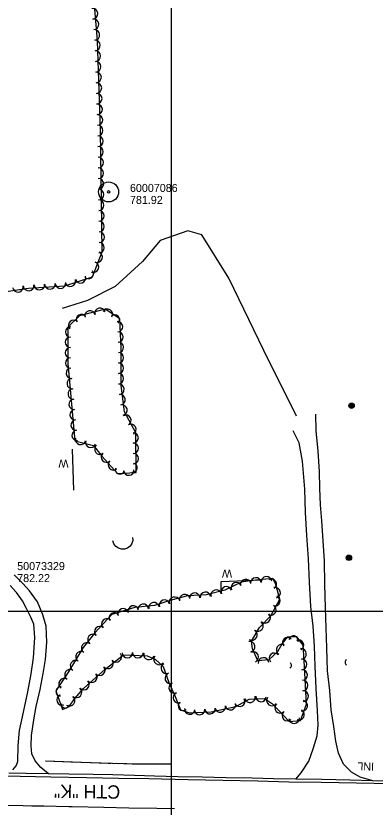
# Model space of a CAD drawing. Extents: x 591954 to 597000, y 198576 to 213500.
# Drawn here: x 592883 to 593152, y 204853 to 205446 of the extents above; entities that cross this region are included whole.
import ezdxf

# ---------------------------------------------------------------- set-up
doc = ezdxf.new("R2010")
doc.units = 0
for name, color, linetype in [('Level 10', 7, 'Continuous'), ('Level 11', 7, 'Continuous'), ('Level 12', 7, 'Continuous'), ('Level 14', 7, 'Continuous'), ('Level 15', 7, 'Continuous'), ('Level 17', 7, 'Continuous'), ('Level 18', 7, 'Continuous'), ('Level 19', 7, 'Continuous'), ('Level 3', 7, 'Continuous'), ('Level 6', 7, 'Continuous')]:
    doc.layers.add(name, color=color, linetype=linetype)

msp = doc.modelspace()

# ---------------------------------------------------------------- linework, layer by layer
at = {"layer": 'Level 10'}
for p, q in [((593000, 204500), (593000, 206000)), ((592000, 205000), (594000, 205000)), ((592000, 205000), (594000, 205000)), ((593000, 203500), (593000, 205000))]:
    msp.add_line(p, q, dxfattribs=at)
at = {"layer": 'Level 11'}
for points in [[(592724.48, 204879.47), (592725.78, 204879.44), (592741.99, 204879.18), (592763.93, 204878.81), (592780.35, 204878.35), (592798.44, 204878.1), (592816.58, 204877.66), (592846.97, 204877.14), (592865.91, 204876.86), (592886.57, 204876.35), (592909.64, 204875.89), (592936.24, 204875.46), (592960.11, 204874.97), (592983.05, 204874.55), (593012.39, 204873.93), (593038.27, 204873.38), (593064.7, 204872.76), (593087.76, 204872.24), (593112.14, 204871.86), (593138.46, 204871.33), (593164.84, 204870.93)], [(593165.37, 204872.59), (593150.8, 204872.76), (593133.45, 204873.25), (593112.63, 204873.78), (593093.15, 204874.12), (593076.42, 204874.43), (593060.27, 204874.94), (593040.92, 204875.23), (593023.03, 204875.6), (593004.69, 204875.96), (592987.26, 204876.44), (592972.27, 204876.83), (592956.03, 204877.24), (592941.19, 204877.5), (592922.95, 204877.85), (592907.87, 204878.05), (592891.06, 204878.27), (592878.05, 204878.66)], [(592895.38, 204853.95), (592888.74, 204854.02), (592868.89, 204854.3)], [(592923.03, 204853.33), (592904.37, 204853.84), (592895.38, 204853.95)], [(593002.1, 204851.87), (592988.95, 204852.07), (592967.96, 204852.44), (592949.24, 204852.79), (592925.52, 204853.26), (592923.03, 204853.33)]]:
    msp.add_lwpolyline(points, dxfattribs=at)
at = {"layer": 'Level 12'}
msp.add_lwpolyline([(592970.84, 205055.37), (592970.9, 205053.02), (592970.22, 205050.77), (592968.88, 205048.84), (592967.02, 205047.42), (592964.8, 205046.64), (592962.45, 205046.59), (592960.2, 205047.27), (592958.27, 205048.61), (592956.85, 205050.48), (592956.07, 205052.7)], dxfattribs=at)
at = {"layer": 'Level 14'}
for centre, radius in [((593134.82, 205154.08), 2.02), ((593134.82, 205154.1), 1.52), ((593134.83, 205154.06), 1.01), ((593134.83, 205154.07), 0.502), ((593132.79, 205040.08), 2.02), ((593132.79, 205040.09), 1.52), ((593132.79, 205040.05), 1.01), ((593132.8, 205040.06), 0.502)]:
    msp.add_circle(centre, radius, dxfattribs=at)
at = {"layer": 'Level 15'}
for points in [[(592925.44, 205121.49), (592926.45, 205090.87)], [(593037.15, 205014.76), (593037.13, 205022.26), (593055.37, 205022.94), (593067.36, 205023.53)]]:
    msp.add_lwpolyline(points, dxfattribs=at)
for centre, start, end in [((593132.43, 204961.86), 128.87943, 235.11899), ((593087.34, 204959.51), 302.27944, 48.519)]:
    msp.add_arc(centre, 2.5, start, end, dxfattribs=at)
at = {"layer": 'Level 17'}
for points in [[(593093.68, 205146.24), (593069.14, 205195.41), (593042.97, 205249.64), (593022.68, 205282.31), (593012.13, 205285.23), (592991.4, 205277.93), (592978.3, 205262.29), (592957.67, 205243.58), (592937.04, 205232.99), (592918.09, 205227.11)], [(593150.8, 204872.76), (593141.2, 204875.62), (593134.78, 204879.29), (593128.77, 204885.4), (593125.07, 204893.56), (593123.13, 204902.73), (593121.45, 204913.58), (593119.56, 204926.09), (593118.43, 204940.58), (593116.83, 204955.29), (593116.25, 204972.61), (593115.73, 204987.62), (593115.21, 205002.64), (593114.84, 205020.19), (593114.45, 205037.69), (593113.47, 205052.69), (593112.66, 205067.76), (593111.61, 205079.84), (593111.17, 205092.35), (593110.74, 205104.86), (593109.8, 205120.08), (593108.33, 205135.3), (593107.96, 205147.79)], [(593093.15, 204874.12), (593097.19, 204878.9), (593102.89, 204887.52), (593106.02, 204896.74), (593109, 204906.55), (593109.69, 204914.55), (593109.25, 204925.64), (593108.42, 204941.99), (593107.5, 204958.77), (593107.07, 204973.86), (593106.14, 204988.73), (593104.32, 205003.61), (593103.34, 205021.83), (593102.52, 205039.34), (593101.19, 205056.71), (593100.44, 205074.08), (593099.83, 205091.6), (593098.19, 205112.48), (593095.5, 205126.35), (593091.16, 205135.15)], [(592907.87, 204878.05), (592902.05, 204882.74), (592897.69, 204887.79), (592895.42, 204893.2), (592894.81, 204899.01), (592895.12, 204906.76), (592896.69, 204918.67), (592898.67, 204928.62), (592901.44, 204941.39), (592903.8, 204953.37), (592905.52, 204963.88), (592906.49, 204976.87), (592905.94, 204988.75), (592903.44, 204997.33), (592899.59, 205007), (592893.53, 205015.23), (592888.69, 205020.72), (592882.2, 205027.34)], [(592881.07, 204881.02), (592883.67, 204884.2), (592884.77, 204887.31), (592885, 204899.41), (592886.16, 204910.59), (592888.95, 204924.23), (592892.29, 204939.55), (592894.89, 204953.12), (592896.55, 204965.1), (592897.45, 204980.33), (592896.76, 204990.31), (592894.45, 204995.5), (592891.39, 205002.12), (592888.2, 205007.84), (592883.79, 205014.12), (592879.19, 205019.23)]]:
    msp.add_lwpolyline(points, dxfattribs=at)
at = {"layer": 'Level 18'}
for points in [[(592867.59, 205238.56), (592892.8, 205242.34), (592920.02, 205244.06), (592940.88, 205250.78), (592947.96, 205269.6), (592947.41, 205307.89), (592946.75, 205360.3), (592944.59, 205427.95), (592941.72, 205460.35)], [(592927.47, 205127.86), (592941.52, 205124.28), (592947.8, 205116.18), (592959.47, 205103.24), (592973.37, 205104.11), (592973.31, 205133.71), (592964.64, 205149.46), (592962.21, 205169.31), (592962.21, 205196.98), (592961.25, 205219.19), (592950.16, 205226.55), (592930.99, 205221.43), (592922.19, 205213), (592922.17, 205185.72), (592927.47, 205127.86)], [(593059.91, 204977.68), (593065.97, 204987.93), (593074.23, 204996.49), (593081.1, 205009.11), (593077.83, 205020.89), (593075.87, 205024.65), (593060.39, 205023.09), (593052.27, 205021.74), (593039.99, 205015.9), (593026.19, 205012.28), (593011.94, 205011.54), (592999.72, 205008.26), (592987.18, 205004.44), (592972.39, 205002.86), (592955.3, 204997.58), (592942.47, 204983.92), (592933.86, 204972.79), (592922.38, 204953.82), (592913.32, 204940.3), (592918.35, 204926.4), (592923.16, 204928.55), (592927.41, 204934.5), (592934.06, 204942.18), (592949.96, 204956.32), (592963.9, 204967.4), (592981.63, 204966.52), (592988.01, 204963.84), (592993.75, 204958.67), (592997.9, 204946.48), (593002.67, 204936.05), (593006.64, 204926.13), (593013.39, 204923.85), (593029.71, 204924.7), (593048.1, 204928.63), (593058.12, 204934.06), (593069.52, 204934.6), (593075.7, 204930.56), (593088.01, 204917.44), (593096.6, 204918.13), (593100.96, 204930.23), (593099.38, 204963.16), (593098.55, 204974.55), (593093.88, 204980.92), (593086.5, 204980.47), (593082.89, 204975.79), (593079.33, 204969.62), (593072.95, 204963.69), (593064.61, 204962.92), (593060.58, 204971.78), (593059.91, 204977.68)]]:
    msp.add_lwpolyline(points, dxfattribs=at)
for centre, radius, start, end in [((592940.71, 205448.01), 4, 275.06839, 95.05306), ((592941.42, 205440.05), 4, 275.06187, 95.04655), ((592942.12, 205432.09), 4, 275.06902, 95.05369), ((592942.61, 205424.23), 4, 271.97988, 91.96456), ((592942.87, 205416.25), 4, 271.82892, 91.8136), ((592943.12, 205408.26), 4, 271.83632, 91.82099), ((592943.38, 205400.28), 4, 271.83632, 91.82099), ((592943.63, 205392.29), 4, 271.83632, 91.82099), ((592943.89, 205384.3), 4, 271.83609, 91.82076), ((592944.14, 205376.32), 4, 271.82915, 91.81383), ((592944.4, 205368.33), 4, 271.83632, 91.82099), ((592944.62, 205360.36), 4, 271.29837, 91.28305), ((592944.76, 205352.39), 4, 270.7318, 90.71648), ((592944.86, 205344.4), 4, 270.7318, 90.71648), ((592944.96, 205336.41), 4, 270.72472, 90.70939), ((592945.06, 205328.42), 4, 270.7318, 90.71648), ((592945.16, 205320.43), 4, 270.7318, 90.71648), ((592945.26, 205312.44), 4, 270.7318, 90.71648), ((592945.37, 205304.44), 4, 270.83226, 90.81694), ((592945.48, 205296.45), 4, 270.83933, 90.82401), ((592945.6, 205288.46), 4, 270.83943, 90.82411), ((592945.72, 205280.47), 4, 270.84649, 90.83117), ((592945.65, 205272.62), 3.96, 267.96122, 87.9459), ((592944.22, 205265.58), 4, 249.37526, 69.35993), ((592941.4, 205258.1), 4, 249.38196, 69.36664), ((592937.92, 205252.96), 3.62, 217.04204, 37.02672), ((592924.12, 205247.58), 4, 197.87579, 17.86047), ((592931.72, 205250.03), 4, 197.87579, 17.86047), ((592884.87, 205243.27), 4, 188.52814, 8.51282), ((592892.89, 205244.28), 3.99, 185.90248, 5.88716), ((592900.93, 205244.95), 4, 183.6238, 3.60848), ((592908.91, 205245.45), 4, 183.62335, 3.60803), ((592916.8, 205246.06), 3.98, 185.35319, 5.33787), ((592938.93, 205221.44), 3.9, 14.95043, 194.93511), ((592946.47, 205223.45), 3.9, 14.95043, 194.93511), ((592951.96, 205222.74), 3.83, 329.02081, 149.00548), ((592926.68, 205214.47), 3.9, 43.78216, 223.76684), ((592932.34, 205218.81), 3.78, 29.82589, 209.81057), ((592957.46, 205218.6), 3.6, 314.51816, 134.50284), ((592959.46, 205213.37), 3.9, 272.49785, 92.48253), ((592924.33, 205209.33), 3.85, 88.02708, 268.01176), ((592924.22, 205201.65), 3.9, 89.96361, 269.94828), ((592959.8, 205205.57), 3.9, 272.49753, 92.48221), ((592960.07, 205197.81), 3.9, 271.52824, 91.51291), ((592924.21, 205193.85), 3.9, 89.97095, 269.95563), ((592960.17, 205190.06), 3.9, 270.00032, 89.985), ((592924.37, 205186.14), 3.9, 92.38259, 272.36727), ((592924.88, 205178.46), 3.9, 95.24264, 275.22732), ((592960.17, 205182.26), 3.9, 269.99298, 89.97765), ((592960.17, 205174.46), 3.9, 269.99298, 89.97765), ((592925.59, 205170.69), 3.9, 95.236, 275.22068), ((592960.58, 205166.47), 3.9, 275.87549, 95.86016), ((592926.3, 205162.92), 3.9, 95.24264, 275.22732), ((592927.02, 205155.15), 3.9, 95.24331, 275.22799), ((592961.45, 205158.68), 3.9, 276.99333, 96.97801), ((592962.86, 205150.86), 3.85, 283.02462, 103.00929), ((592927.73, 205147.38), 3.9, 95.24331, 275.22799), ((592965.78, 205143.16), 3.9, 298.83904, 118.82372), ((592928.44, 205139.61), 3.9, 95.24264, 275.22732), ((592969.54, 205136.32), 3.9, 298.84258, 118.82726), ((592929.13, 205131.88), 3.86, 95.2431, 275.22778), ((592931.84, 205128.85), 3.9, 165.73989, 345.72457), ((592971.23, 205129.97), 3.89, 270.86957, 90.85425), ((592939.36, 205126.49), 3.79, 160.1923, 340.17698), ((592946.26, 205121.51), 3.9, 127.78668, 307.77136), ((592971.29, 205122.21), 3.9, 270.12514, 90.10982), ((592951.14, 205115.59), 3.9, 131.36426, 311.34894), ((592971.31, 205114.41), 3.9, 270.13249, 90.11717), ((592956.32, 205109.79), 3.9, 132.04673, 312.0314), ((592970.97, 205107.63), 3.32, 257.9527, 77.93738), ((592961.32, 205106.3), 3.53, 163.62773, 343.61241), ((592967.95, 205105.81), 3.9, 183.58629, 3.57096), ((593048.57, 205017.68), 3.97, 25.46977, 205.45444), ((593055.55, 205020.04), 3.95, 11.65152, 191.6362), ((593063.18, 205021.24), 3.97, 6.39087, 186.37555), ((593071.06, 205022.07), 3.97, 5.73548, 185.72015), ((593075.05, 205020.47), 3.61, 301.12911, 121.11379), ((593033.38, 205012.02), 3.97, 14.71379, 194.69846), ((593041.12, 205014.51), 3.96, 20.85277, 200.83745), ((593077.6, 205013.97), 3.97, 285.49047, 105.47515), ((593002.24, 205006.75), 3.97, 15.49934, 195.48402), ((593009.84, 205008.69), 3.96, 13.08251, 193.06719), ((593017.3, 205009.74), 3.97, 2.96549, 182.95017), ((593025.35, 205010.46), 3.95, 7.2819, 187.26658), ((593077.51, 205007.81), 3.79, 250.15324, 70.13792), ((592971.25, 205000.12), 3.96, 14.11939, 194.10407), ((592978.75, 205001.45), 3.97, 6.09858, 186.08326), ((592986.75, 205002.62), 3.96, 10.48806, 190.47274), ((592994.66, 205004.55), 3.97, 16.95767, 196.94235), ((593074.36, 205001.08), 3.97, 241.46512, 61.4498), ((592957.06, 204995.11), 3.84, 31.12363, 211.1083), ((592963.72, 204998), 3.97, 17.20423, 197.18891), ((593070.05, 204995.16), 3.97, 226.24759, 46.23227), ((592951.53, 204990.53), 3.97, 46.79279, 226.77747), ((593064.76, 204988.98), 3.95, 232.54089, 52.52557), ((592946.14, 204984.73), 3.97, 47.41612, 227.40079), ((592941.14, 204978.79), 3.97, 52.29397, 232.27864), ((593060.19, 204982.23), 3.97, 239.4211, 59.40578), ((593086.84, 204976.63), 3.72, 42.0738, 222.05848), ((593091.38, 204977.97), 3.57, 347.44754, 167.43222), ((592936.45, 204972.49), 3.97, 54.52456, 234.50923), ((593058.64, 204973.47), 3.89, 280.83259, 100.81726), ((593082.41, 204971.14), 3.95, 57.77331, 237.75798), ((593095.2, 204974.69), 3.84, 296.74277, 116.72745), ((592932.18, 204965.99), 3.97, 58.83243, 238.81711), ((592958.63, 204965.87), 3.97, 218.49741, 38.48209), ((592966.79, 204968.9), 3.85, 182.59638, 2.58106), ((592974.8, 204968.94), 3.97, 177.15786, 357.14254), ((592982.98, 204967.61), 3.92, 164.6531, 344.63778), ((593061.2, 204965.6), 3.93, 295.39233, 115.37701), ((593076.97, 204964.74), 3.94, 41.60922, 221.59389), ((593096.94, 204968.05), 3.97, 274.18679, 94.17147), ((592928.07, 204959.19), 3.97, 58.82869, 238.81337), ((592952.41, 204960.92), 3.97, 218.49741, 38.48209), ((592990.59, 204963.84), 3.93, 142.68743, 322.67211), ((593068.89, 204961.23), 3.97, 5.30133, 185.28601), ((593097.43, 204960.16), 3.97, 272.94389, 92.92857), ((592923.84, 204952.4), 3.97, 57.36995, 237.35463), ((592946.24, 204955.76), 3.97, 221.33811, 41.32279), ((592995.96, 204957.16), 3.89, 115.03925, 295.02393), ((593097.83, 204952.23), 3.97, 272.75627, 92.74094), ((592940.28, 204950.49), 3.97, 221.65557, 41.64025), ((592999.05, 204949.75), 3.97, 109.7275, 289.71218), ((592919.46, 204945.72), 3.97, 56.1836, 236.16828), ((592934.38, 204945.09), 3.97, 223.29145, 43.27612), ((593001.98, 204942.56), 3.97, 114.56321, 294.54789), ((593098.21, 204944.3), 3.97, 272.75627, 92.74094), ((592916.94, 204939.84), 3.54, 83.20149, 263.18616), ((592928.74, 204939.22), 3.97, 229.12089, 49.10556), ((593005.18, 204935.21), 3.97, 112.59534, 292.58002), ((593098.59, 204936.36), 3.97, 272.74906, 92.73374), ((592917.99, 204933.51), 3.97, 109.89773, 289.88241), ((592923.69, 204932.9), 3.96, 233.58193, 53.56661), ((593050.97, 204932.55), 3.97, 208.45006, 28.43474), ((593058.8, 204935.44), 3.88, 192.50122, 12.48589), ((593067.01, 204936.07), 3.86, 176.40447, 356.38914), ((593075.13, 204933.11), 3.95, 143.42054, 323.40522), ((593097.96, 204929.17), 3.91, 256.5561, 76.54078), ((592920.35, 204930.25), 2.83, 173.99972, 353.98439), ((593008.58, 204929.18), 3.63, 129.92534, 309.91001), ((593013.61, 204926.63), 3.9, 171.65951, 351.64419), ((593021.03, 204926.33), 3.97, 183.0159, 3.00058), ((593028.79, 204926.99), 3.96, 186.80878, 6.79346), ((593036.42, 204928.26), 3.97, 192.06011, 12.04479), ((593044.14, 204929.97), 3.96, 192.92211, 12.90679), ((593081.31, 204927.62), 3.97, 133.18701, 313.17169), ((593086.75, 204921.83), 3.97, 133.18175, 313.16643), ((593095.65, 204922.31), 3.77, 244.88185, 64.86653), ((593091.75, 204919.85), 3.96, 184.05251, 4.03719)]:
    msp.add_arc(centre, radius, start, end, dxfattribs=at)
at = {"layer": 'Level 19'}
for points in [[(592999.57, 204885.45), (592972.43, 204885.4), (592947.33, 204886.1), (592924.52, 204886.76), (592905.48, 204887.69)], [(592954.57, 204885.9), (592952.58, 204885.95), (592905.87, 204887.65)], [(592960.57, 204885.73), (592958.57, 204885.78)], [(592966.57, 204885.56), (592964.57, 204885.62)], [(592999.57, 204885.45), (592972.43, 204885.4), (592970.57, 204885.45)]]:
    msp.add_lwpolyline(points, dxfattribs=at)
at = {"layer": 'Level 6'}
for radius in [7.5, 0.96]:
    msp.add_circle((592952.83, 205314.38), radius, dxfattribs=at)

# ---------------------------------------------------------------- texts
at = {"layer": 'Level 15'}
for s, rotation, p in [('W', 180.94133, (592922.73, 205113.68)), ('W', 178.94133, (593045.43, 205031.14)), ('INL', 178.79289, (593151.76, 204886.5))]:
    msp.add_text(s, height=6, rotation=rotation, dxfattribs=at).set_placement(p)
at = {"layer": 'Level 3'}
msp.add_text('CTH "K"', height=10, rotation=179.14575, dxfattribs=at).set_placement((592961.6, 204869.43))
at = {"layer": 'Level 6'}
for s, p in [('60007086', (592968.83, 205314.38)), ('781.92', (592968.83, 205305.38)), ('50073329', (592884.35, 205030.87)), ('50073329', (592884.35, 205030.87)), ('50073329', (592884.35, 205030.87)), ('782.22', (592884.35, 205021.87)), ('782.22', (592884.35, 205021.87)), ('782.22', (592884.35, 205021.87))]:
    msp.add_text(s, height=6, dxfattribs=at).set_placement(p)

doc.saveas('drawing.dxf')
